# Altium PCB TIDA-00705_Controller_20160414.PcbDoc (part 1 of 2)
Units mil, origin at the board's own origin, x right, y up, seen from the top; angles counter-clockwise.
Board outline 1000 x 1000 mil, 4 copper layers (Top Layer, L2-GND-PLANE, L3-GND-PLANE, Bottom Layer), stack 0 mil thick; 95 components, 61 nets, 268 pads, 111 vias.
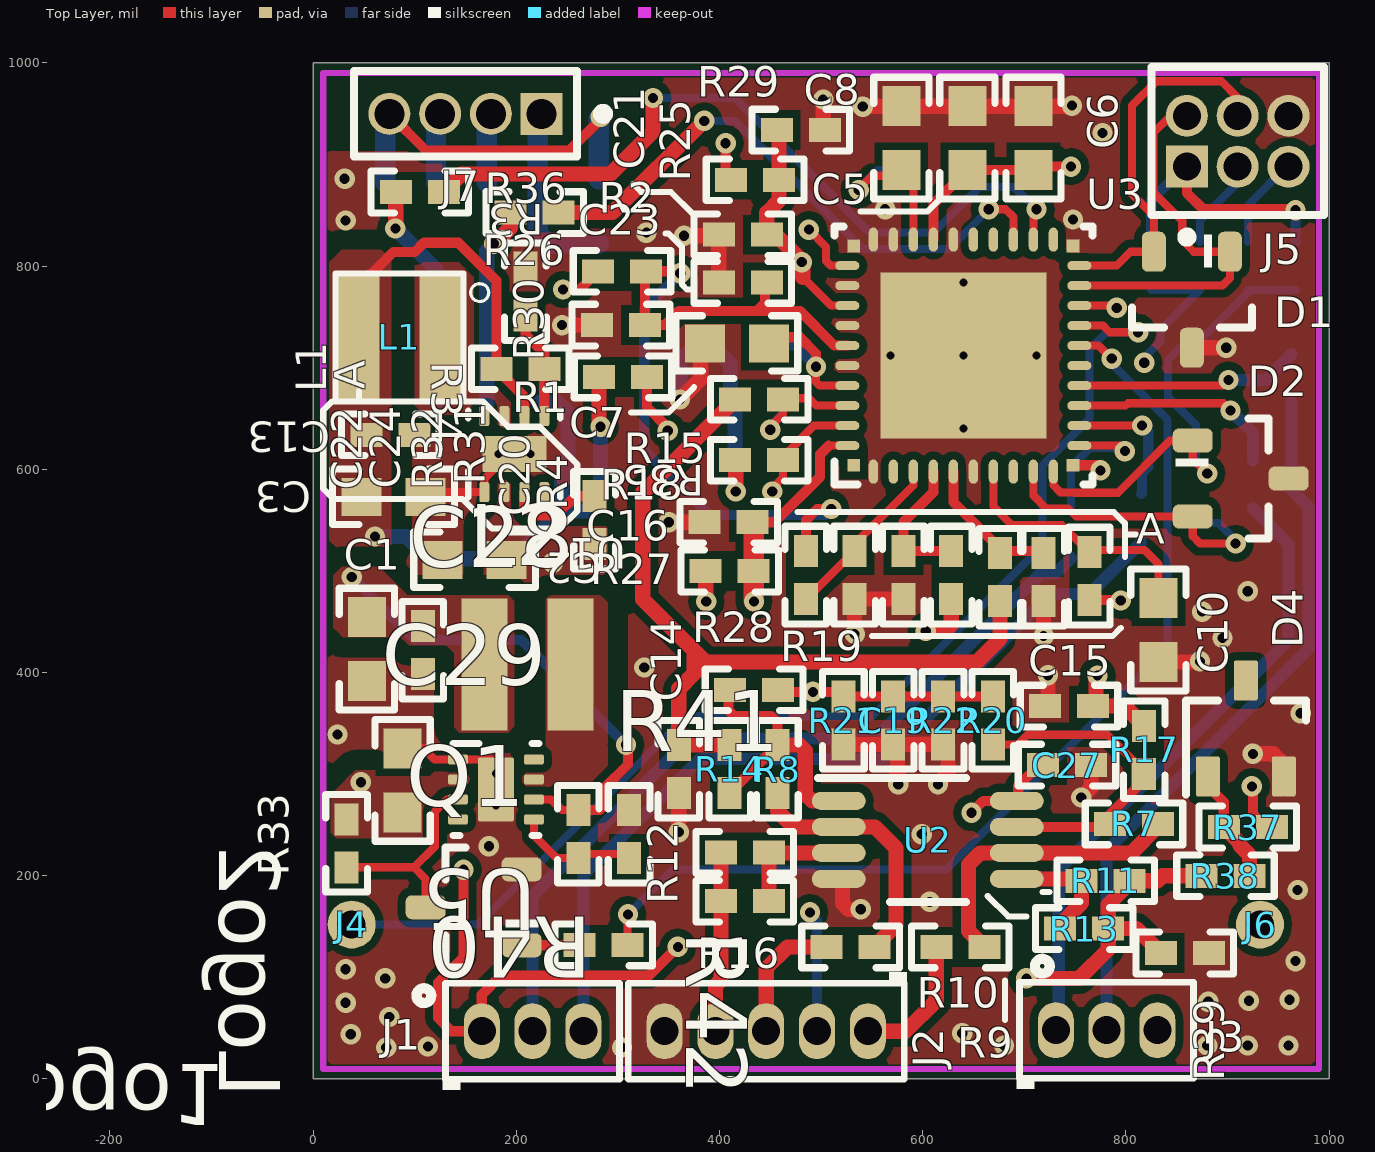
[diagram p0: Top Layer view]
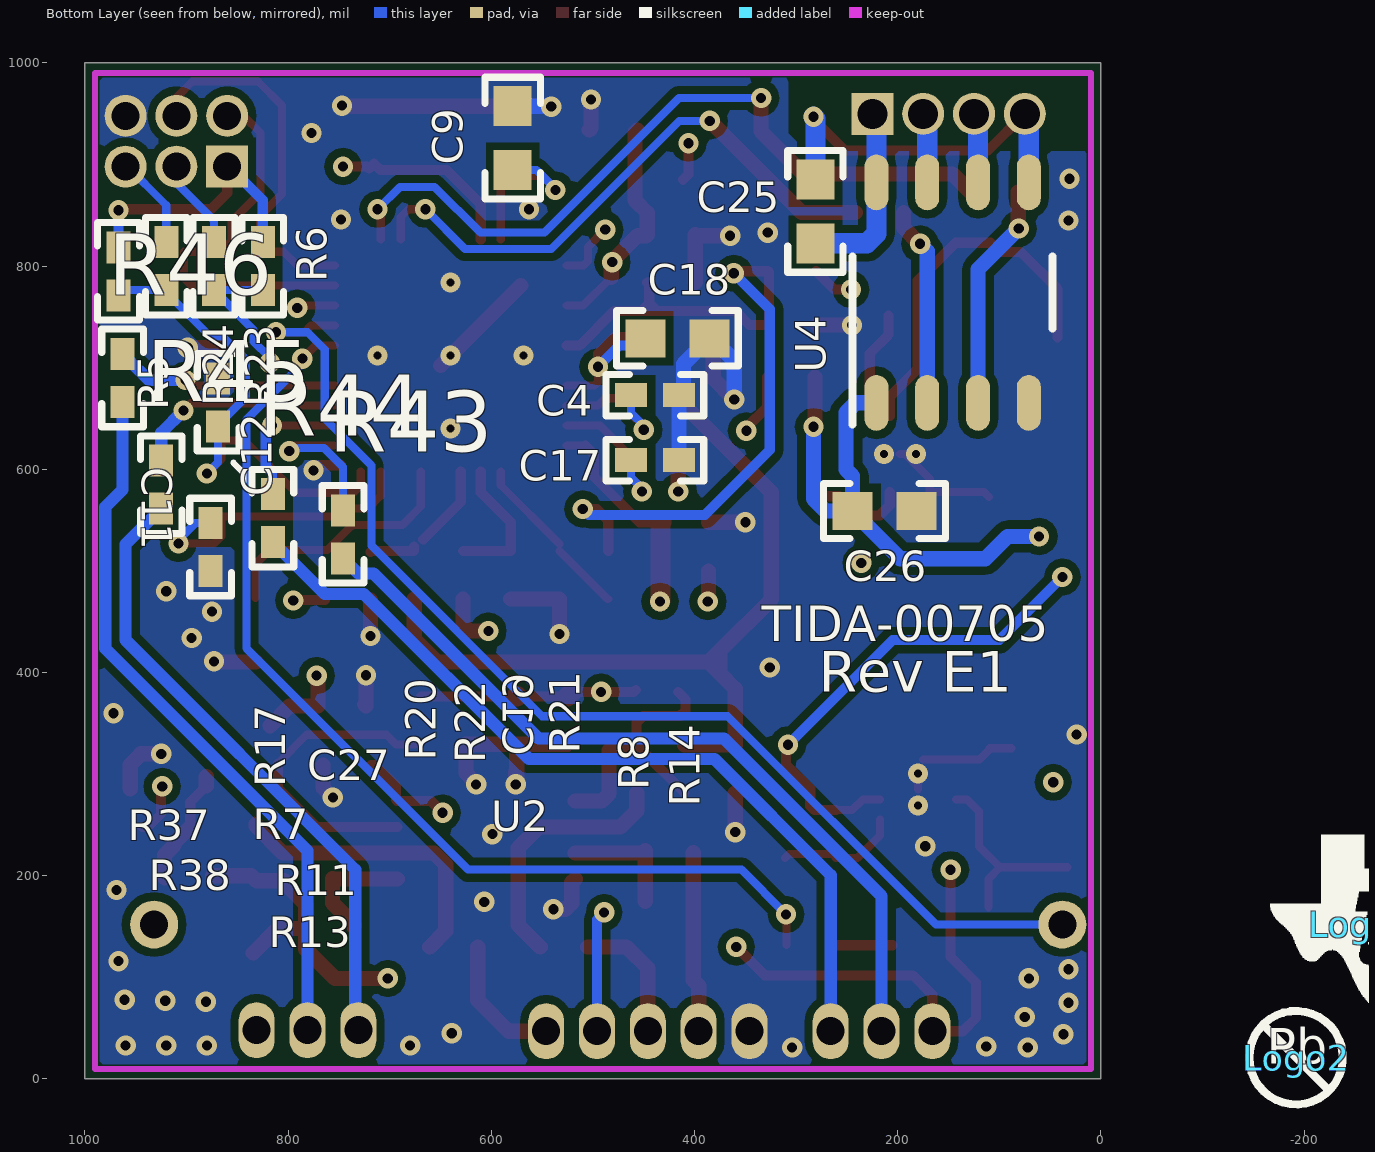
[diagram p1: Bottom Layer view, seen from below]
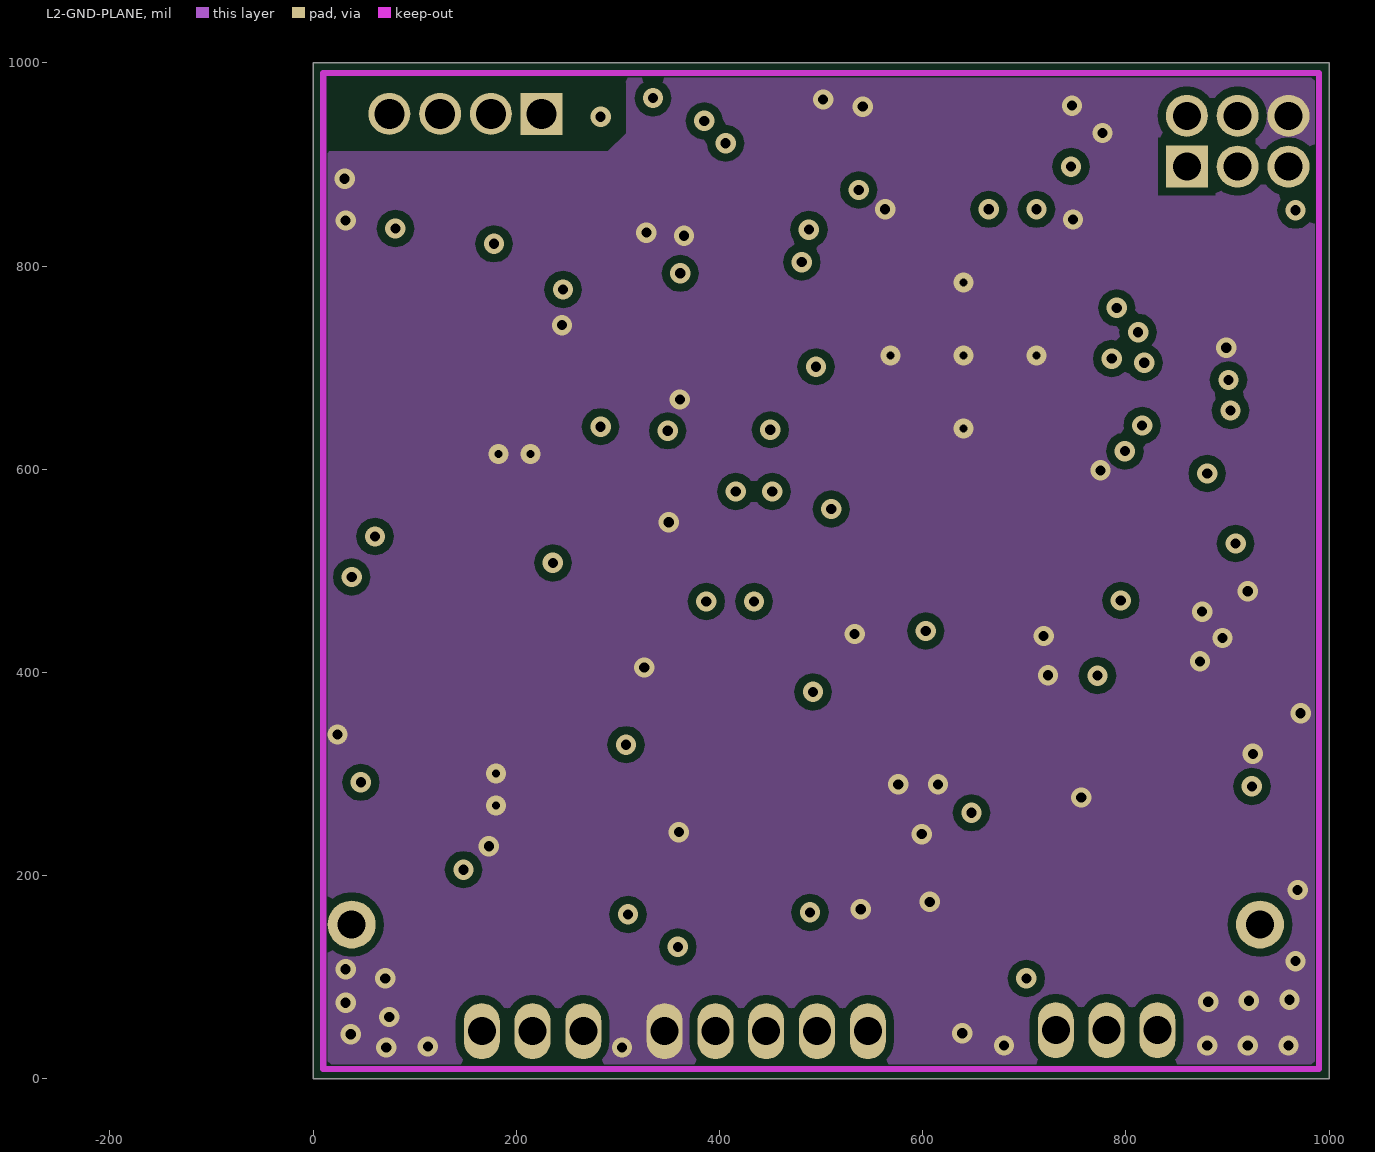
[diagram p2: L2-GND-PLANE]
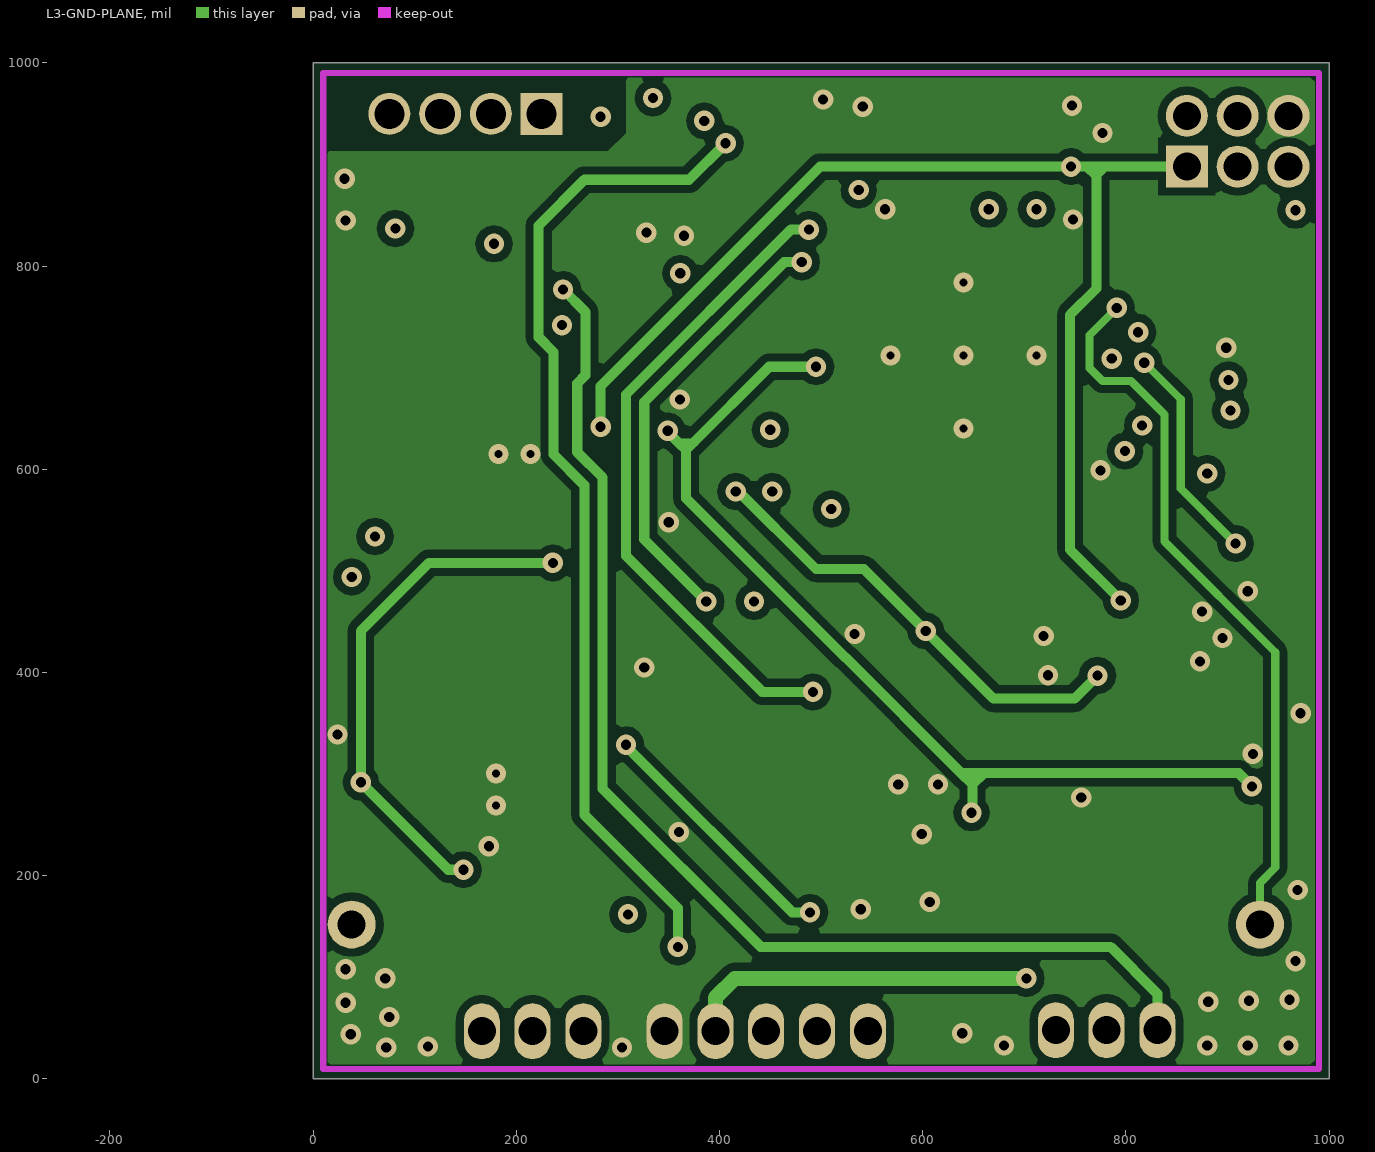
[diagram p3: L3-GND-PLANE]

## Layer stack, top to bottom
Top Layer: signal copper (thickness not stored)
L2-GND-PLANE: signal copper (thickness not stored)
L3-GND-PLANE: signal copper (thickness not stored)
Bottom Layer: signal copper (thickness not stored)

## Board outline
0,0 1000,0 1000,1000 0,1000

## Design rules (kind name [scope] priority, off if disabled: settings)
AcuteAngle [All] p1: minimum=4.50000000000000E+0001 checktracksonly=FALSE
AssemblyTestPointUsage [All] p1: valid=2
Clearance kEEPOUT-POLY [Iskeepout vs InPolygon] p1: gap=1
Clearance "Keepout - Track" [IsKeepOut vs IsTrack] p2: gap=1
Clearance "U7 AND U9 Pad Class" [(InPadClass('Less Than 7.7')) vs (InPadClass('Less Than 7.7'))] p3: gap=7.8
Clearance "Clearance_Poly to Poly" [InPolygon vs InPolygon] p4: gap=20
Clearance "Clearance_VIA TO VIA" [IsVia vs IsVia] p5: gap=8
Clearance "Clearance_Via to SMD" [IsVia vs IsSMTPin] p6: gap=8
Clearance Clearance_BoardEdge_MountingHoles [OnCopper and InComponentClass('Mounting Holes') vs IsKeepOut] p7: gap=40
Clearance Clearance_Poly [InPolygon vs IsTrack and IsVia and IsSMTPin and IsThruPin] p8: gap=12
Clearance [All] p9: gap=8
ComponentClearance ComponentClearance_Logo [InComponentClass('Logo')] p1: gap=50 collisioncheckmode=3 verticalgap=10 showdistances=FALSE
ComponentClearance ComponentClearance_ScrewToNut [(HasFootprint('NY PMS 440 0025 PH')) vs (HasFootprint('Keystone_1902C'))] p2: gap=5 collisioncheckmode=3 verticalgap=10 showdistances=FALSE
ComponentClearance ComponentClearance_MountingHoles [InComponentClass('Mounting Holes')] p3: gap=250 collisioncheckmode=3 verticalgap=100000 showdistances=FALSE
ComponentClearance ComponentClearance_SmallPassives [HasFootprint('0201*') or HasFootprint('0402*') or HasFootprint('0508') or HasFootprint('0603*') or HasFootprint('0612') or HasFootprint('0805*') or HasFootprint('0815*') or HasFootprint('0830*') or HasFootprint('1206*') or HasFootprint('1210*') or HasFootprint('1808*') or HasFootprint('1812*') or HasFootprint('1825*') or HasFootprint('2010*') or HasFootprint('2220*') or HasFootprint('2225*') or HasFootprint('2512*') or HasFootprint('2728*') or HasFootprint('3518*') vs HasFootprint('0201*') or HasFootprint('0402*') or HasFootprint('0508') or HasFootprint('0603*') or HasFootprint('0612') or HasFootprint('0805*') or HasFootprint('0815*') or HasFootprint('0830*') or HasFootprint('1206*') or HasFootprint('1210*') or HasFootprint('1808*') or HasFootprint('1812*') or HasFootprint('1825*') or HasFootprint('2010*') or HasFootprint('2220*') or HasFootprint('2225*') or HasFootprint('2512*') or HasFootprint('2728*') or HasFootprint('3518*')] p4: gap=20 collisioncheckmode=3 verticalgap=10 showdistances=FALSE
ComponentClearance ComponentClearance_THtoSMT [IsThruComponent vs IsSMTComponent] p5: gap=100 collisioncheckmode=3 verticalgap=30 showdistances=FALSE
ComponentClearance ComponentClearance_THtoTH [IsThruComponent vs IsThruComponent] p6: gap=118.11 collisioncheckmode=3 verticalgap=30 showdistances=FALSE
ComponentClearance [All] p7: gap=40 collisioncheckmode=3 verticalgap=10 showdistances=FALSE
DiffPairsRouting DiffPair_DiffPairsRouting [InDifferentialPair ('OP AMP')] p1: maxlimit=8 minlimit=8 mostfreqgap=8 toplayer_minwidth=8 toplayer_maxwidth=8 toplayer_prefwidth=8 midlayer1_minwidth=8 midlayer1_maxwidth=8 midlayer1_prefwidth=8 midlayer2_minwidth=8 midlayer2_maxwidth=8 midlayer2_prefwidth=8 bottomlayer_minwidth=8 bottomlayer_maxwidth=8 bottomlayer_prefwidth=8 maxuncoupledlength=500
DiffPairsRouting DiffPair_DiffPairsRouting_1 [InDifferentialPair ('OP AMP')] p2: maxlimit=10 minlimit=10 mostfreqgap=8 toplayer_minwidth=15 toplayer_maxwidth=15 toplayer_prefwidth=8 midlayer1_minwidth=15 midlayer1_maxwidth=15 midlayer1_prefwidth=8 midlayer2_minwidth=15 midlayer2_maxwidth=15 midlayer2_prefwidth=8 bottomlayer_minwidth=15 bottomlayer_maxwidth=15 bottomlayer_prefwidth=8 maxuncoupledlength=500
DiffPairsRouting [All] p3: maxlimit=100 minlimit=10 mostfreqgap=10 toplayer_minwidth=15 toplayer_maxwidth=15 toplayer_prefwidth=15 midlayer1_minwidth=15 midlayer1_maxwidth=15 midlayer1_prefwidth=15 midlayer2_minwidth=15 midlayer2_maxwidth=15 midlayer2_prefwidth=15 bottomlayer_minwidth=15 bottomlayer_maxwidth=15 bottomlayer_prefwidth=15 maxuncoupledlength=1000
FabricationTestPointUsage TestPointUsage [All] p1: valid=2 allowmultiple=FALSE
FabricationTestpoint Testpoint [All] p1: side=3 testpointundercomponent=TRUE minsize=40 maxsize=100 preferedsize=60 minholesize=0 maxholesize=40 preferedholesize=32 testpointgrid=1 allowsidetop=TRUE allowsidebottom=TRUE usegrid=TRUE gridtolerance=0.01
FanoutControl Fanout_LCC [IsLCC] p1: bgadir=Out bgaviamode=Centered fanoutstyle=Auto fanoutdirection=Alternating viagrid=1 // Fanout_LCC (Default Rule)
FanoutControl Fanout_BGA [IsBGA] p2: bgadir=Out bgaviamode=Centered fanoutstyle=Auto fanoutdirection=Alternating viagrid=1 // Fanout_BGA (Default Rule)
FanoutControl Fanout_Default [All] p4: bgadir=Out bgaviamode=Centered fanoutstyle=Auto fanoutdirection=Alternating viagrid=1 // Fanout_Default (Default Rule)
FanoutControl Fanout_Small [(CompPinCount < 5)] p5: bgadir=Out bgaviamode=Centered fanoutstyle=Auto fanoutdirection=OutThenIn viagrid=1 // Fanout_Small (Default Rule)
HoleSize [All] p1: absolutevalues=TRUE maxlimit=251 minlimit=7.8 maxpercent=80.000 minpercent=20.000
MatchedLengths DiffPair_MatchedLengths [InDifferentialPair ('OP AMP')] p1: tolerance=1000 checknetsindiffpair=TRUE checkdiffpairvsdiffpair=TRUE checkothers=TRUE
MatchedLengths DiffPair_MatchedLengths_1 [InDifferentialPair ('OP AMP')] p2: tolerance=1000 checknetsindiffpair=TRUE checkdiffpairvsdiffpair=TRUE checkothers=TRUE
MinimumAnnularRing MinimumAnnularRing_ThermalPadVias [IsVia and InAnyComponent] p1: minimumring=5.91
MinimumAnnularRing [All] p2: minimumring=5
MinimumSolderMaskSliver MinimumSolderMaskSliver_Logo [InComponentClass('Logo') vs InComponentClass('Logo')] p1: minsoldermaskwidth=0.7
MinimumSolderMaskSliver [All] p2: minsoldermaskwidth=3.94
PlaneClearance [All] p1: clearance=16
PlaneConnect [All] p1: planeconnectstyle=Direct reliefexpansion=10 reliefentries=4 reliefconductorwidth=10 reliefairgap=10
PolygonConnect [All] p1: connectstyle=Direct reliefconductorwidth=10 reliefentries=4 polygonreliefangle="90 Angle" airgapwidth=10
RoutingVias RoutingVias_PWR [InNetClass('PWR')] p1: holewidth=10 width=20 viastyle="Through Hole" minholewidth=10 minwidth=20 maxholewidth=10 maxwidth=20
RoutingVias [InNetClass('All Nets')] p2: holewidth=10 width=20 viastyle="Through Hole" minholewidth=10 minwidth=20 maxholewidth=10 maxwidth=20
RoutingVias ThermalPadVias [IsVia and InAnyComponent] p3: holewidth=7.87 width=19.68 viastyle="Through Hole" minholewidth=7.87 minwidth=19.68 maxholewidth=12.99 maxwidth=23.62
SMDToCorner [All] p1: distance=30000
SilkToSilkClearance [All] p1: silktosilkclearance=5
SilkToSolderMaskClearance SilkscreenOverComponentPads [IsPad] p1 off: minsilkscreentomaskgap=5 clearancetoexposedcopper=TRUE
SolderMaskExpansion [All] p1: expansion=2.5
UnpouredPolygon [All] p1: allowunpoured=FALSE
Width Width_PWR [InNetClass('PWR')] p1: maxlimit=100 minlimit=8 preferedwidth=20
Width [All] p2: maxlimit=100 minlimit=6 preferedwidth=8 checkconnectedcopper=TRUE
14 further rules are at their usual default settings.

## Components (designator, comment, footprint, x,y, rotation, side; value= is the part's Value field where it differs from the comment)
C1 "CC0603KRX5R7BB475" 0603 53,423 r90 top
C2 "CC0603KRX5R7BB475" 0603 159,511 r0 top
C3 "CC0603KRX5R7BB475" 0603 79,573 r180 top
C4 "GRM1535C1H101JDD5D" 0402 439,673 r180 bottom
C5 "C0603C104K4RACTU" 0603 644,926 r270 top
C6 "CC0603KRX5R7BB475" 0603 709,926 r270 top
C7 "C0603C104K4RACTU" 0603 417,724 r0 top
C8 "C0603C104K4RACTU" 0603 579,926 r270 top
C9 "C0603C105K4PACTU" 0603 579,926 r90 bottom
C10 "C0603C104K4RACTU" 0603 832,442 r270 top
C11 "885012005043" 0402 869,666 r90 bottom
C12 "885012005043" 0402 876.38,523.62 r270 bottom
C13 "GRM1535C1H101JDD5D" 0402 76,634 r0 top
C14 "GRM1535C1H101JDD5D" 0402 360,305 r270 top
C15 "GRM1535C1H101JDD5D" 0402 744,367 r180 top
C16 "GRM1535C1H101JDD5D" 0402 409,548 r180 top
C17 "GRM1535C1H101JDD5D" 0402 439,609 r180 bottom
C18 "CC0603KRX5R7BB475" 0603 417,729 r0 bottom
C19 "GRM1535C1H101JDD5D" 0402 571,353 r270 top
C20 "GRM1535C1H101JDD5D" 0402 719,494 r270 top
C21 "GRM1535C1H101JDD5D" 0402 423,831 r180 top
C22 "GRM1535C1H101JDD5D" 0402 533,496 r270 top
C23 "GRM1535C1H101JDD5D" 0402 423,784 r180 top
C24 "GRM1535C1H101JDD5D" 0402 581,496 r270 top
C25 "08053C104KAT2A" 0603 281,854 r90 bottom
C26 "08053C104KAT2A" 0603 213,559 r180 bottom
C27 "C0603C104K4RACTU" 0402 742,309 r180 top
C28 "GRM1535C1H101JDD5D" 0402 108,422 r270 top
C29 "CC0603KRX5R7BB475" 0603 88,294 r270 top
D1 "SDM20N40A-7-F" SOT-23 865,767 r270 top
D2 "SDM20N40A-7-F" SOT-23 913,591 r0 top
D4 "LM4041B12IDBZR" DBZ0003A_N 918,345 r90 top
J1 "GRPB031VWVN-RC" Sullins_GRPB031VWVN-RC 216,47 r0 top
J2 "GRPB051VWVN-RC" Sullins_GRPB051VWVN-RC 446,47 r180 top
J3 "GRPB031VWVN-RC" Sullins_GRPB031VWVN-RC 781,48 r0 top
J4 "PEC01SAAN" SULLINS_PEC01SAAN#1 137.01,137.01 r0 top
J5 "GRPB032VWVN-RC" Sullins_GRPB032VWVN-RC 910,923 r90 top
J6 "PEC01SAAN" SULLINS_PEC01SAAN#2 850,137.99 r180 top
J7 "GRPB041VWVN-RC" Sullins_GRPB041VWVN-RC 150,950 r180 top
L1 "3.3uH" LQH3NP_G0 85,730 r180 top
L2 "3.3uH" LQH3NP_G0 211,408 r180 top
Logo1 "Texas Instruments" TI_Symbol_Overlay_Small -257,152 r180 bottom
Logo2 "Pb-Free Symbol" Pb-Free_Overlay_Small -192,21 r180 bottom
Q1 "BC847CLT1G" SOT-23 158,169 r180 top
R1 "CRCW08051R00FKEA" 0402 305,691 r180 top
R2 "CRCW08051R00FKEA" 0402 218,852.75 r0 top
R3 "CRCW04023K16FKED" 0402 209,775 r270 top
R4 "CRCW04021K65FKED" 0402 764,495 r270 top
R5 "CRCW04021K50FKED" 0402 967,795 r90 bottom
R6 "CRCW04021K50FKED" 0402 825,800 r90 bottom
R7 "CRCW04021K05FKED" 0402 808,251 r180 top
R8 "CRCW04021K05FKED" 0402 457,305 r90 top
R9 "CRCW04021K05FKED" 0402 637,130 r0 top
R10 "CRCW04021K05FKED" 0402 529,130 r0 top
R11 "CRCW04021K05FKED" 0402 780,195 r180 top
R12 "CRCW04021K05FKED" 0402 425,223 r0 top
R13 "CRCW04021K05FKED" 0402 759,148 r180 top
R14 "CRCW04021K05FKED" 0402 410,305 r90 top
R15 "CRCW04021K05FKED" 0402 439,669 r0 top
R16 "CRCW04021K05FKED" 0402 425,175 r0 top
R17 "CRCW04021K05FKED" 0402 818,324 r90 top
R18 "CRCW04021K05FKED" 0402 439,609 r0 top
R19 "CRCW04021K05FKED" 0402 434,383 r180 top
R20 "CRCW04021K05FKED" 0402 669,353 r270 top
R21 "CRCW04021K05FKED" 0402 522,353 r90 top
R22 "CRCW04021K05FKED" 0402 620,353 r90 top
R23 "CRCW0402100RFKED" 0402 873,800 r90 bottom
R24 "CRCW0402100RFKED" 0402 920,800 r90 bottom
R25 "CRCW04021K65FKED" 0402 435,885 r180 top
R26 "CRCW04021K65FKED" 0402 304,795 r180 top
R27 "CRCW04021K65FKED" 0402 410,500 r180 top
R28 "CRCW04021K65FKED" 0402 485,496 r90 top
R29 "CRCW04021K65FKED" 0402 480,934 r180 top
R30 "CRCW04021K65FKED" 0402 303,742 r0 top
R31 "CRCW04021K05FKED" 0402 676,494 r270 top
R32 "CRCW04021K05FKED" 0402 628,496 r270 top
R33 "CRCW040210K2FKED" 0402 33,232 r90 top
R34 "CRCW040210K2FKED" 0402 204,699 r180 top
R35 "CRCW040210K2FKED" 0402 277,550 r270 top
R36 "CRCW08051R00FKEA" 0402 105,873 r0 top
R37 "CRCW04021K05FKED" 0402 920,248 r0 top
R38 "CRCW04021K05FKED" 0402 898,200 r0 top
R39 "CRCW04021K05FKED" 0402 858,124 r180 top
R40 "CRCW040210K2FKED" 0402 261,241 r90 top
R41 "CRCW04023K16FKED" 0402 311,241 r270 top
R42 "CRCW040210K2FKED" 0402 286,132 r180 top
R43 "CRCW0402100RFKED" 0402 746,536.15 r270 bottom
R44 "CRCW0402100RFKED" 0402 815,552 r270 bottom
R45 "CRCW0402100RFKED" 0402 925,585 r270 bottom
R46 "CRCW0402100RFKED" 0402 963,690 r270 bottom
U1 "TPS62125DSGR" DSG0008A 198,615 r90 top
U2 "OPA2192IDGKR" DGK0008A_N 605,235.33 r0 top
U3 "UCD3138RMHR" RMH0040A 640,712 r90 top
U4 "ISO7321CDR" D0008B_N 146,774 r90 bottom
U5 "TPS62125DSGR" DSG0008A 180,285 r0 top

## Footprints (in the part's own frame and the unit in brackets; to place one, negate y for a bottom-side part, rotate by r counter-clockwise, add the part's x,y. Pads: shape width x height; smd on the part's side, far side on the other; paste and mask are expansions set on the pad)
0402 [mm] "0402 from SM-752 data"
  rect 0.8x0.6 smd: 1(-0.6,0) 2(0.6,0)
  silkscreen extent -1.22,-0.52 1.22,0.52, body extent -0.55,-0.3 0.55,0.3, height 0.6
0603 [mm] "0603 from SM-752 data"
  rect 1x0.95 smd: 1(-0.8,0) 2(0.8,0)
  silkscreen extent -1.52,-0.69 1.52,0.69, body extent -0.87,-0.47 0.87,0.47, height 1
D0008B_N [mil] "SOIC, 8-Leads, Body 4.9x3.9mm, Pitch 1.27mm, IPC Medium Density"
  oval 55x23.62 smd: 1(-108.5,75) 2(-108.5,25) 3(-108.5,-25) 4(-108.5,-75) 5(108.5,-75) 6(108.5,-25) 7(108.5,25) 8(108.5,75)
  silkscreen extent -130,-98 35,98, body extent -118,-96 118,96, height 64
DBZ0003A_N [mm] "SOT23, 3-Leads, Body 2.9x1.3mm, Pitch 0.95mm, Lead Span 2.4mm, IPC Medium Density"
  rrect17% 1x0.6 smd: 1(-1.2,0.95) 2(-1.2,-0.95) 3(1.2,0)
  silkscreen extent -1.65,-1.5 0.7,1.5, body extent -1.26,-1.46 1.26,1.46, height 0.98
DGK0008A_N [mm] "TSOP, 8-Leads, Body 3x3mm, Pitch 0.65mm, IPC Medium Density"
  oval 1.35x0.45 smd: 1(-2.225,0.975) 2(-2.225,0.325) 3(-2.225,-0.325) 4(-2.225,-0.975) 5(2.225,-0.975) 6(2.225,-0.325) 7(2.225,0.325) 8(2.225,0.975)
  silkscreen extent -2.75,-1.55 0.95,1.55, body extent -2.45,-1.5 2.45,1.5, height 0.96
DSG0008A [mm] "SON, 8-Leads, Body 2x2mm, Pitch 0.5mm, Thermal Pad 1.6x0.9mm, TI Recommended"
  rrect40% 0.5x0.25 smd: 1(-0.95,0.75) 2(-0.95,0.25) 3(-0.95,-0.25) 4(-0.95,-0.75) 5(0.95,-0.75) 6(0.95,-0.25) 7(0.95,0.25) 8(0.95,0.75)
  rrect11% 0.9x1.6 smd paste-0.45: 9(0,0)
  silkscreen extent -1.07,-1.15 1.07,1.15, body extent -1.05,-1.05 1.05,1.05, height 0.8
LQH3NP_G0 [mm] "MURATA"
  rect 1.15x3.3 smd: 1(-1.075,0) 2(1.075,0)
  silkscreen extent -2.23,-1.6 1.6,1.6, body extent -1.6,-1.6 1.6,1.6, height 1.01
Pb-Free_Overlay_Small [mil]
  silkscreen extent -46,-46 46,46
RMH0040A [mm] "QFN, 40-Leads, Body 6x6mm, Pitch 0.5mm, Thermal Pad 4.15x4.15mm"
  oval 0.6x0.23 smd: 1(-2.9,2.25) 2(-2.9,1.75) 3(-2.9,1.25) 4(-2.9,0.75) 5(-2.9,0.25) 6(-2.9,-0.25) 7(-2.9,-0.75) 8(-2.9,-1.25) 9(-2.9,-1.75) 10(-2.9,-2.25) 21(2.9,-2.25) 22(2.9,-1.75) 23(2.9,-1.25) 24(2.9,-0.75) 25(2.9,-0.25) 26(2.9,0.25) 27(2.9,0.75) 28(2.9,1.25) 29(2.9,1.75) 30(2.9,2.25)
  oval 0.23x0.6 smd: 11(-2.25,-2.9) 12(-1.75,-2.9) 13(-1.25,-2.9) 14(-0.75,-2.9) 15(-0.25,-2.9) 16(0.25,-2.9) 17(0.75,-2.9) 18(1.25,-2.9) 19(1.75,-2.9) 20(2.25,-2.9) 31(2.25,2.9) 32(1.75,2.9) 33(1.25,2.9) 34(0.75,2.9) 35(0.25,2.9) 36(-0.25,2.9) 37(-0.75,2.9) 38(-1.25,2.9) 39(-1.75,2.9) 40(-2.25,2.9)
  rect 4.15x4.15 smd paste-4.15: 41(0,0)
  rect 0.32x0.32 smd: 42(-2.74,2.74) 43(-2.74,-2.74) 44(2.74,-2.74) 45(2.74,2.74)
  silkscreen extent -3.22,-3.22 3.22,3.22, body extent -3.08,-3.08 3.08,3.08, height 0.8
SOT-23 [mm] "SOT23, 3-Leads, Body 2.9x1.3mm, Pitch 0.95mm, Lead Span 2.5mm, IPC Medium Density"
  rrect50% 1x0.6 smd: 1(-1.2,0.95) 2(-1.2,-0.95) 3(1.2,0)
  silkscreen extent -1.62,-1.5 0.7,1.5, body extent -1.16,-1.45 1.21,1.45, height 1
Sullins_GRPB031VWVN-RC [mm] "SULLINS"
  oval 0.9x1.4 hole 0.7: 1(-1.27,0) 2(0,0) 3(1.27,0)
  silkscreen extent -2.25,-1.47 2.17,1.2, body extent -2.15,-1.17 2.17,1.17, height 4.2
Sullins_GRPB032VWVN-RC [mm] "Sullins"
  rect 1.05x1.05 hole 0.7 paste+0: 1(-0.635,1.27)
  round 1.05 hole 0.7 paste+0: 2(0.635,1.27) 3(-0.635,0) 4(0.635,0) 5(-0.635,-1.27) 6(0.635,-1.27)
  silkscreen extent -2.51,-2.15 1.85,2.15, body extent -1.85,-2.15 1.85,2.15, height 4
Sullins_GRPB041VWVN-RC [mm] "TH, Header, 1.27 mm, 4x1, Straight"
  rect 1.05x1.05 hole 0.75: 1(-1.905,0)
  round 1.05 hole 0.75: 2(-0.635,0) 3(0.635,0) 4(1.905,0)
  silkscreen extent -3.54,-1.07 2.79,1.07, body extent -2.79,-1.07 2.79,1.07, height 4.3
Sullins_GRPB051VWVN-RC [mm] "SULLINS"
  oval 0.9x1.4 hole 0.7: 1(-2.54,0) 2(-1.27,0) 3(0,0) 4(1.27,0) 5(2.54,0)
  silkscreen extent -3.52,-1.47 3.45,1.2, body extent -3.42,-1.17 3.42,1.17, height 4.2
SULLINS_PEC01SAAN#1 [mm] "SULLINS"
  round 1.2 hole 0.7: 1(-2.515,0.381)
  body extent -3.59,-1.07 -0.99,1.53, height 8.38
SULLINS_PEC01SAAN#2 [mm] "SULLINS"
  round 1.2 hole 0.7: 1(-2.083,-0.356)
  body extent -3.43,-1.73 -0.83,0.87, height 8.38
TI_Symbol_Overlay_Small [mil]
  silkscreen extent -90,-88 91,88

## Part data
C1 C2 C3 C6 C18 C29: library part GRM188R61C475KAAJ, "CAP, CERM, 4.7 µF, 16 V, +/- 10%, X5R, 0603"
C4 C13 C14 C15 C16 C17 C19 C20 C21 C22 C23 C24 C28: "CAP, CERM, 100 pF, 50 V, +/- 5%, C0G/NP0, 0402"
C5 C7 C8 C10 C27: "CAP, CERM, 0.1 µF, 16 V, +/- 10%, X7R, 0603"
C9: "CAP, CERM, 1 µF, 16 V, +/- 10%, X5R, 0603"
C11 C12: "CAP, CERM, 33 pF, 25 V, +/- 5%, C0G/NP0, 0402"
C25 C26: "CAP, CERM, 0.1 µF, 25 V, +/- 10%, X7R, 0805"
D1 D2: "Diode, Schottky, 40 V, 0.2 A, SOT-23"
D4: "Precision Micropower Shunt Voltage Reference, 0.2% accuracy, 1.2 V, 15 ppm / degC, 12 mA, -40 to 85 degC, 3-pin SOT-23 (DBZ), Green (RoHS & no Sb/Br)"
J1 J3: "Header, 50mil, 3x1, Gold, TH"
J2: "Header, 50mil, 5x1, Gold, TH"
J4 J6: "Header, 1x1, Tin, TH"
J5: "Header, 50mil, 3x2, Gold, TH"
J7: "Header, 50mil, 4x1, Gold, TH"
L1 L2: library part LQH3NPN101MG0, "Inductor, Wirewound, Ferrite, 100 µH, 0.14 A, 8 ohm, SMD"
Logo1: library part TI_Logo, "Texas Instrument Corporate Signature"
Logo2: library part Pb-Free
Q1: library part "BC847CLT1G, ON Semiconductor", "Transistor, NPN, 45 V, 0.1 A, SOT-23"
R1 R2 R36: "RES, 1.00, 1%, 0.125 W, 0805"
R3 R41: "RES, 3.16 k, 1%, 0.063 W, 0402"
R4 R25 R26 R27 R28 R29 R30: "RES, 1.65 k, 1%, 0.063 W, 0402"
R5 R6: "RES, 1.50 k, 1%, 0.063 W, 0402"
R7 R8 R9 R10 R11 R12 R13 R14 R15 R16 R17 R18 R19 R20 R21 R22 R31 R32 R37 R38 R39: "RES, 1.05 k, 1%, 0.063 W, 0402"
R23 R24 R43 R44 R45 R46: "RES, 100, 1%, 0.063 W, 0402"
R33 R34 R35 R40 R42: "RES, 10.2 k, 1%, 0.063 W, 0402"
U1 U5: "3V-17V, 300mA Step Down Converter With Adjustable Enable Threshold And Hysteresis, DSG0008A"
U2: "36-V, Precision, Rail-to-Rail Input/Output, Low Offset Voltage, Low Input Bias Current Op Amp with e-trim, DGK0008A"
U3: "Highly Integrated Digital Controller for Isolated Power, RMH0040A"
U4: "Robust EMC, Low Power, Dual-Channel Digital Isolators, D0008B"

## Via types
v1: diameter 20, hole 10, Top Layer to Bottom Layer, tented both sides, 76 vias
v2: diameter 20, hole 10, Top Layer to Bottom Layer, 26 vias
v3: diameter 19.68, hole 7.87, Top Layer to Bottom Layer, tented both sides, 5 vias
v4: diameter 19.68, hole 7.87, Top Layer to Bottom Layer, 4 vias

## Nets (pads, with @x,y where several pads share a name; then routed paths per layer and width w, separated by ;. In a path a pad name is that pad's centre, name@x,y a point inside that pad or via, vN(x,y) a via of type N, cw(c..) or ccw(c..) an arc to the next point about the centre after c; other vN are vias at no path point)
3.3V: C3.2 C5.2 C6.2 C13.1 C26.1 J5.1 L1.2 R1.2 R4.2 R5.2 R6.2 R34.2 U1.6 U3.27 U4.1 | length 2535.4
  Top Layer w10: L1.2@42.68,730 42.68,777.68 79,814 100,814 109,823 143,823 180.38,785.62 R34.2@180.38,699 207.84,671.54 U1.6@207.84,652.4 ; U3.27@610.47,826.17 610.47,860.98 C5.2@644,894.5 C6.2@709,894.5 715.5,901 720.5,896 722.5,898 v1(746,898) ; R4.2@764,471.38 794.62,471.38 v1(795,471) ; J5.1@860,900 J5.1@860,898 860,872 876,856 966,856 v1(967,855)
  Top Layer w15: R1.2@281.38,691 281.38,643.62 v1(283,642)
  L3-GND-PLANE w10: v1(283,642) 283,682.1 498.9,898 v1@744,898 ; v1(746,898) 762,898 ; v1@794.62,471.38 745,521 745,752.04 771,778.04 771,889 ; J5.1@858,898 778,898 ; 762,898 778,898 ; 762,898 771,889 ; 771,889 771,890 778,897 778,898
  Bottom Layer w10: R6.2@825,823.62 825,865 J5.1@860,900 ; R5.2@967,823.62 v1(967,855)
  Bottom Layer w15: v2(61,534) 92,534 114,512 197.5,512 C26.1@244.5,559 ; U4.1@221,665.5 241.5,665.5 251,656 251,600 244.5,593.5 C26.1@244.5,559 ; v1(283,642) 283,571 271,559 C26.1@244.5,559
3.3V_ISO: C25.1 J7.1 U4.8 | length 183.6
  Bottom Layer w20: J7.1@225,950 221,946 U4.8@221,882.5 221,832 230.5,822.5 C25.1@281,822.5
3.3VA: C7.2 C18.2 C27.2 R1.1 R37.2 U2.8 U3.37 | length 1352.7
  Top Layer w8: v1(495,701) 495,686 498.53,682.47 U3.37@525.83,682.47
  Top Layer w10: R1.1@328.62,691 328.62,661.38 349,641 v1(349,638) ; C7.2@448.5,730 479,730 495,714 v1@495,696 ; v1(648,262) 659.72,273.72 U2.8@692.6,273.72 694,275.12 694,288.5 714.5,309 C27.2@718.38,309 ; v1(924,288) 925.13,286.87 925.13,260.87 938,248 R37.2@943.62,248
  L3-GND-PLANE w10: v1(349,638) 349,637 360.5,625.5 ; 375,627 373.5,625.5 ; v1(495,701) 449,701 373.5,625.5 ; v1(648,262) 649,263 649,290 ; v1(924,288) 911,301 660,301 ; 360.5,625.5 373.5,625.5 ; 360.5,625.5 367,619 ; 367,619 367,571.47 523.47,415 524,415 638,301 ; 367,619 373.5,625.5 ; 638,301 649,290 ; 638,301 660,301 ; 649,290 660,301
  Bottom Layer w10: C18.2@465,722 474,722 v1(495,701)
8.2V: C1.2 C28.1 J2.2 L2.2 R40.2 U5.6 | length 854.1
  Top Layer w8: U5.6@217.4,275.16 234.34,275.16 244.88,264.62 R40.2@261,264.62
  Top Layer w10: R40.2@261,264.62 281.81,264.62 286.19,269 286.19,285.75 310,309.57 310,327 v2(308,329)
  L3-GND-PLANE w10: v2(308,329) 308,327.53 471.53,164 v2(489,164)
  Bottom Layer w10: v2(38,494) 100,432 205,432 v2(308,329) ; v2(489,164) 496,157 J2.2@496,47
ARMED: J4.1 U3.17 | length 1162.3
  Top Layer w8: U3.17@754.17,741.53 777.36,741.53 783.89,735 v1(812,735)
  Bottom Layer w8: J4.1@38,152 162.54,152 367.54,357 550.11,357 718,524.89 718,604 764,650 764,718.11 780.89,735 v1(812,735)
BAT+: J3.3 R26.2 | length 1221.6
  Top Layer w10: v1(246,777) 262.38,777 R26.2@280.38,795
  L3-GND-PLANE w10: v1(246,777) 268,755 268,692.56 260,684.56 260,617 285,592 285,285.47 440.47,130 785,130 831,84 J3.3@831,48
BAT_REV_PROT: J6.1 U3.18 | length 754.4
  Top Layer w8: U3.18@754.17,761.21 788.79,761.21 v1(791,759)
  L3-GND-PLANE w8: v1(791,759) 764,732 764,699.89 776.89,687 804.91,687 838,653.91 838,529 947,420 947,208 932,193 J6.1@932,152
BAT_VSENADC: C22.1 R28.1 U3.3 | length 162.7
  Top Layer w8: R28.1@485,472.38 485.76,472.38 C22.1@533,519.62 ; C22.1@533,526.62 590.79,584.41 U3.3@590.79,597.83
BAT_VSENEADC: C23.1 R26.1 R28.2 R30.2 U3.35 | length 812.9
  Top Layer w10: v1(361.37,793) 361.37,792.37 360,791 356,795 R26.1@327.62,795 326.62,794 R30.2@326.62,742 346,742 360,756 437.24,756 ; C23.1@446.62,784 444.62,782 444.62,763.38 ; 452,756 444.62,763.38 ; R28.2@485,519.62 485,550 496,561 v1(510,561) ; U3.35@525.83,721.84 513.16,721.84 479,756 437.24,756 ; 437.24,756 444.62,763.38
  Bottom Layer w10: v1(361.37,793) 326,757.63 326,619 389.81,555.19 504.19,555.19 v1(510,561)
BUS+: C2.2 C29.2 J1.1 R25.2 R33.2 R35.2 U1.2 U5.2 | length 1978.1
  Top Layer w10: v2(148,206) 148,120 123,95 123,60 136,47 J1.1@166,47 166,83 185,102 331,102 v1(359,130) ; v1(406,921) 406,890.38 R25.2@411.38,885
  L3-GND-PLANE w10: v2(148,206) 133,206 v2(47,292) 47,441 114,508 v2(236,508) ; v1(359,130) 359,168 267,260 267,584.54 236.59,614.95 236.59,715.41 222,730 222,840 267,885 370,885 v1(406,921)
BUS_VSENADC: C16.1 R27.1 U3.40 | length 216
  Top Layer w8: 507.42,623.42 U3.40@525.83,623.42
  Top Layer w10: C16.1@432.62,548 454.21,548 499,592.79 499,615 507.42,623.42
  Top Layer w20: C16.1@432.62,548 433.62,547 R27.1@433.62,500 433.62,470.38 v1(434,470)
BUS_VSENEADC: C21.1 R25.1 R27.2 R29.2 U3.33 | length 693.5
  Top Layer w8: C21.1@446.62,831 C21.1@450.5,831 ; 482,789 509.79,761.21 U3.33@525.83,761.21
  Top Layer w15: R27.2@386.38,500 386.38,470.62 v1(387,470) ; R29.2@456.38,934 458.62,931.76 R25.1@458.62,885 458.62,864.62 446.62,852.62 C21.1@446.62,831 447.62,830 456,830 482,804 482,789
  L3-GND-PLANE w10: v1(387,470) 326,531 326,666.26 463.74,804 v1(481,804)
GD_EN: R42.1 U3.16 | length 1014.7
  Top Layer w8: R42.1@309.62,132 309.62,161.62 v2(310,162) ; U3.16@754.17,721.84 773.16,721.84 v2(786,709)
  Bottom Layer w8: v2(310,162) 354,206 623.11,206 841,423.89 841,649.21 786,704.21 v2(786,709)
GND: C1.1 C2.1 C3.1 C4.2 C5.1 C6.1 C7.1 C8.1 C9.2 C10.2 C11.2 C12.2 C13.2 C14.2 C15.2 C16.2 C17.2 C18.1 C19.2 C20.2 C21.2 C22.2 C23.2 C24.2 C26.2 C27.1 C28.2 C29.1 D1.3 D2.3 D4.2 J2.5 J5.6 Q1.2 R3.1 R21.1 R22.1 R29.1 R30.1 R39.1 R41.1 U1.1 U1.9 U2.4 U3.1 U3.6 U3.26 U3.29 U3.30 U3.32 U3.34 U3.36 U3.41 U3.43 U3.44 U3.45 U4.4 U5.1 U5.9 | length 1635.4
  Top Layer w8: C29.1@88,325.5 109.7,325.5 109.7,324.3 119.47,314.53 U5.1@142.6,314.53 U5.9@174.87,314.53 ; C3.1@110.5,573 115.09,577.6 U1.1@168.47,577.6 168.47,590.6 192.87,615 U1.9@198,615 ; U5.9@180,285 v4(180,300.75)
  Top Layer w10: U3.43@747.87,604.13 773.87,604.13 777.21,600.79 v1@775.43,599
  Top Layer w15: v1(245,742) R30.1@279.38,742 ; v1(350,548) C16.2@386.38,548 ; C14.2@358.62,280 C14.2@360,281.38 v2(360,243) ; v1(361,668.73) 381.63,689.36 381.63,715.13 C7.1@385.5,719 ; v1(365,830) C21.2@398.38,830 ; C23.2@399.38,784 C21.2@399.38,831 ; v1(502,964) 502,935.62 R29.1@503.62,934 ; U2.4@517.4,196.94 521,193.35 521,173 527,167 v1(539,167) ; R21.1@525,329.38 C19.2@575,329.38 ; v1(533,438) C22.2@533,472.38 C24.2@581,472.38 ; v1(541,957) 541.5,957.5 C8.1@579,957.5 C5.1@644,957.5 C6.1@709,957.5 746.5,957.5 v1(747,958) ; U3.41@571.1,780.9 v3(640,712) U3.41@649.84,702.16 ; 576,302 576,296 575,297 C19.2@575,329.38 ; v1(615,290) 617,292 617,293 625,301 625,329.38 C19.2@575,329.38 ; v1(719,436) C20.2@719,471.38 ; v1(723.38,397.38) 723.38,367 C15.2@725,368.62 ; v1@747.87,845.87 v1(748,846) ; v1(756,277) 765.62,286.62 C27.1@765.62,309 ; v1(775,599) v1@775.43,599 ; C10.2@832,410.5 872.5,410.5 v1(873,411) ; D1.3@865,719.76 v2(898.76,719.76) ; v2@898.76,720 v2@899,720 ; v1(925,320) 945,320 955.4,309.6 D4.2@955.4,297.76 D4.2@955.4,285.7
  Bottom Layer w15: v1(361,668.73) 361,707 372,718 396.5,718 410.81,703.69 410.81,677.57 C4.2@415.38,673 C17.2@415.38,611 ; v1(541,957) 541.5,957.5 C9.2@579,957.5
  other v1: 72,31 304,31 113,32 680,33 880,33 920,33 960,33 37,44 32,75 881,76 921,77 961,78 32,108 967,116 969,186 576,290 972,360 875,460 920,480 328,833 563,856 777,931
  other v2: 639,45 75,61 71,99 607,174.31 173,229 599,241 24,339 326,405 895,434 32,845 31,886
  other v3: 640,640.15 568.15,712 711.85,712 640,783.85
  other v4: 180,269.25 182.25,615 213.75,615
H1_PWM: J1.3 R44.2 | length 838.3
  Bottom Layer w12: J1.3@266,47 266,200.5 380.5,315 563.06,315 725.53,477.47 764.09,477.47 R44.2@815,528.38
H2_PWM: J3.2 R46.2 | length 707.8
  Bottom Layer w12: J3.2@781,48 781,224.72 980,423.72 980,563 963,580 R46.2@963,666.38
IL1: J2.3 R10.1 | length 130.1
  Top Layer w15: J2.3@446,47 446,109 467,130 R10.1@505.38,130
IL2: J2.1 R9.1 | length 132.6
  Top Layer w15: J2.1@546,47 583,47 613.38,77.38 R9.1@613.38,130
IOUT1: C4.1 R15.2 U3.38 | length 136.2
  Top Layer w8: v1@450,643 451,643 462.62,654.62 R15.2@462.62,673 ; R15.2@463.62,670 488,670 495.21,662.79 U3.38@525.83,662.79
  Bottom Layer w8: v1@450,643 462.62,655.62 C4.1@462.62,673
  other v1: 450,639
IOUT2: C17.1 R18.2 U3.39 | length 142
  Top Layer w8: v1@451.87,581.19 462.62,591.94 R18.2@462.62,611 ; R18.2@464.31,614.31 493.1,643.1 U3.39@525.83,643.1
  Bottom Layer w8: v1@451.87,581.19 462.62,591.94 C17.1@462.62,611
  other v1: 451.87,578.19
ISENSE: C19.1 R19.1 R20.1 R21.2 R22.2 U3.31 | length 927.4
  Top Layer w8: v1(488,836) 505,819 505,805 509.42,800.58 U3.31@525.83,800.58
  Top Layer w10: R19.1@457.62,383 459.62,381 v1(492,381) 517.62,381 R21.2@522,376.62 ; R21.2@525,376.62 575,376.62 R20.1@669,376.62
  Top Layer w20: R21.2@520.62,381 R21.2@525,376.62
  L3-GND-PLANE w10: v1(488,836) 470.28,836 308,673.72 308,515 442,381 v1(492,381) v1@496,381
ISO_GND: C25.2 J7.4 U4.5 | length 376.5
  Top Layer w10: J7.4@75,950 111.17,913.83 252.09,913.83 v1@283,944.74
  Top Layer w15: v1@283,944.74 v1(283,947)
  Top Layer w20: J7.4@75,943 J7.4@75,950
  Bottom Layer w20: U4.5@71,882.5 71,946 J7.4@75,950 ; C25.2@281,885.5 281,945 v1(283,947)
L1_PWM: J1.2 R43.2 | length 800.7
  Bottom Layer w12: J1.2@216,47 216,180 371,335 553.57,335 716.04,497.47 730.94,497.47 R43.2@746,512.53
L2_PWM: J3.1 R45.2 | length 622.7
  Bottom Layer w12: J3.1@731,48 734,51 734,206 960,432 960,526.38 R45.2@925,561.38
NetC10_1: C10.1 R4.1 U3.7 | length 253.7
  Top Layer w8: U3.7@669.53,597.83 669.53,563.47 687.63,545.37 735.78,545.37 736.15,545 737.15,545 761.53,520.62 818.38,520.62 832,507 C10.1@832,473.5
NetC20_1: C20.1 R31.1 U3.5 | length 129.9
  Top Layer w10: U3.5@630.16,597.83 630.16,567.84 R31.1@667,531 ; R31.1@676,524 676,519.62 718,519.62 C20.1@719,518.62
NetC24_1: C24.1 R32.1 U3.4 | length 137.4
  Top Layer w10: U3.4@610.47,597.83 610.47,577.47 581,548 C24.1@581,519.62 R32.1@628,519.62
NetD4_1: D4.1 R37.1 R38.2 | length 116.7
  Top Layer w10: D4.1@880.6,288.4 896.38,272.62 R37.1@896.38,248
  Top Layer w15: D4.1@880.6,288.4 D4.1@880.6,297.76 ; R37.1@896.38,248 912.37,232 912.37,229.77 921.62,220.52 R38.2@921.62,200 R38.2@921.62,198
NetJ5_3: J5.3 R23.2 | length 91.7
  Bottom Layer w8: R23.2@873,823.62 873,845 910,882 J5.3@910,900
NetJ5_5: J5.5 R24.2 | length 92.9
  Bottom Layer w8: R24.2@920,823.62 920,860 J5.5@960,900
NetL1_1: L1.1 U1.7
NetL2_1: L2.1 U5.7
NetQ1_1: Q1.1 R42.2 | length 57.3
  Top Layer w10: Q1.1@205.24,131.6 261.98,131.6 R42.2@262.38,132
NetQ1_3: Q1.3 R33.1 U5.3 | length 201.5
  Top Layer w8: R33.1@33,208.38 99.38,208.38 ; Q1.3@110.76,169 110.76,197 99.38,208.38 ; U5.3@142.6,275.16 131.7,275.16 120,263.46 120,229 99.38,208.38
NetR2_1: R2.1 U4.2 | length 197.2
  Top Layer w15: v2(178,822) 178.44,822 194.38,837.94 R2.1@194.38,852.75
  Bottom Layer w15: U4.2@171,665.5 171,815 v2(178,822)
NetR7_1: R7.1 R9.2 U2.6 | length 292
  Top Layer w15: R9.2@660.62,130 645,145.62 645,211 656.54,222.54 U2.6@692.6,222.54 805.39,222.54 831.62,248.76 R7.1@831.62,251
